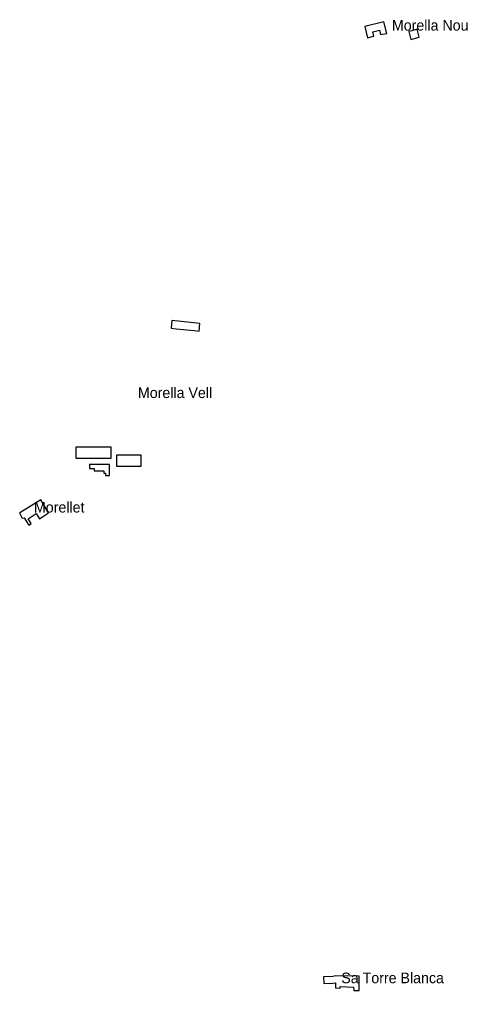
# Model space of a CAD drawing. Extents: x 599451 to 612034, y 4411179 to 4428219.
# Drawn here: x 605674 to 606181, y 4424740 to 4425838 of the extents above; entities that cross this region are included whole.
import ezdxf

# ---------------------------------------------------------------- set-up
doc = ezdxf.new("R2010")
doc.units = 0
doc.layers.add('Bé Arquitectònic', color=7, linetype='Continuous')

msp = doc.modelspace()

# ---------------------------------------------------------------- linework, layer by layer
at = {"layer": 'Bé Arquitectònic'}
for points in [[(606089.4, 4425821.7), (606086.1, 4425834.7), (606064.4, 4425829.4), (606067.5, 4425816.7), (606074.7, 4425818.5), (606073.5, 4425823.6), (606081, 4425825.4), (606082.3, 4425820.4)], [(606125.8, 4425817.5), (606123.6, 4425826.4), (606117.5, 4425824.7), (606114.1, 4425823.8), (606116.6, 4425815)], [(605871.7, 4425485.7), (605877.3, 4425485.1), (605878.2, 4425493.9), (605846.4, 4425497.2), (605845.5, 4425488.4), (605851.2, 4425487.8)], [(605778, 4425353.9), (605738.1, 4425353.9), (605738.1, 4425341.6), (605778, 4425341.6)], [(605772, 4425334.4), (605753.5, 4425334.4), (605753.5, 4425329.7), (605758.6, 4425329.7), (605758.6, 4425327.3), (605769.6, 4425327.3), (605769.6, 4425324.5), (605771.4, 4425324.5), (605771.4, 4425321.8), (605772, 4425321.8), (605775.9, 4425321.8), (605775.9, 4425327.2), (605775.9, 4425334.4)], [(605784, 4425339.4), (605784, 4425332.5), (605789.7, 4425332.5), (605800.6, 4425332.5), (605806.8, 4425332.5), (605811.8, 4425332.5), (605811.8, 4425340.8), (605811.8, 4425345), (605809.1, 4425345), (605806.8, 4425345), (605800.6, 4425345), (605784, 4425345)], [(605701.1, 4425289.8), (605698.4, 4425294.3), (605687.6, 4425287.8), (605674.6, 4425279.9), (605674.2, 4425279.7), (605677.3, 4425273.8), (605679.5, 4425274.1), (605684.2, 4425266.8), (605684.9, 4425265.8), (605687.6, 4425267.5), (605687, 4425268.4), (605684, 4425273.1), (605693.2, 4425278.8), (605696.7, 4425273.1), (605707.1, 4425279.6)], [(606031.7, 4424756.4), (606028.2, 4424755.6), (606017.7, 4424755.1), (606018, 4424747.6), (606028.5, 4424748.2), (606031.4, 4424748.3), (606031.2, 4424742.6), (606036.5, 4424742.3), (606036.7, 4424744.2), (606051.6, 4424743.7), (606051.9, 4424739.9), (606058.2, 4424739.7), (606058.2, 4424742.9), (606058, 4424755.9)]]:
    msp.add_lwpolyline(points, close=True, dxfattribs=at)

# ---------------------------------------------------------------- texts
for s, p in [('Morella Nou', (606095.1, 4425824.9)), ('Morella Vell', (605808.1, 4425409.5)), ('Morellet', (605690.6, 4425280.1)), ('Sa Torre Blanca', (606037.9, 4424748))]:
    msp.add_text(s, height=12, dxfattribs=at).set_placement(p)

doc.saveas('drawing.dxf')
